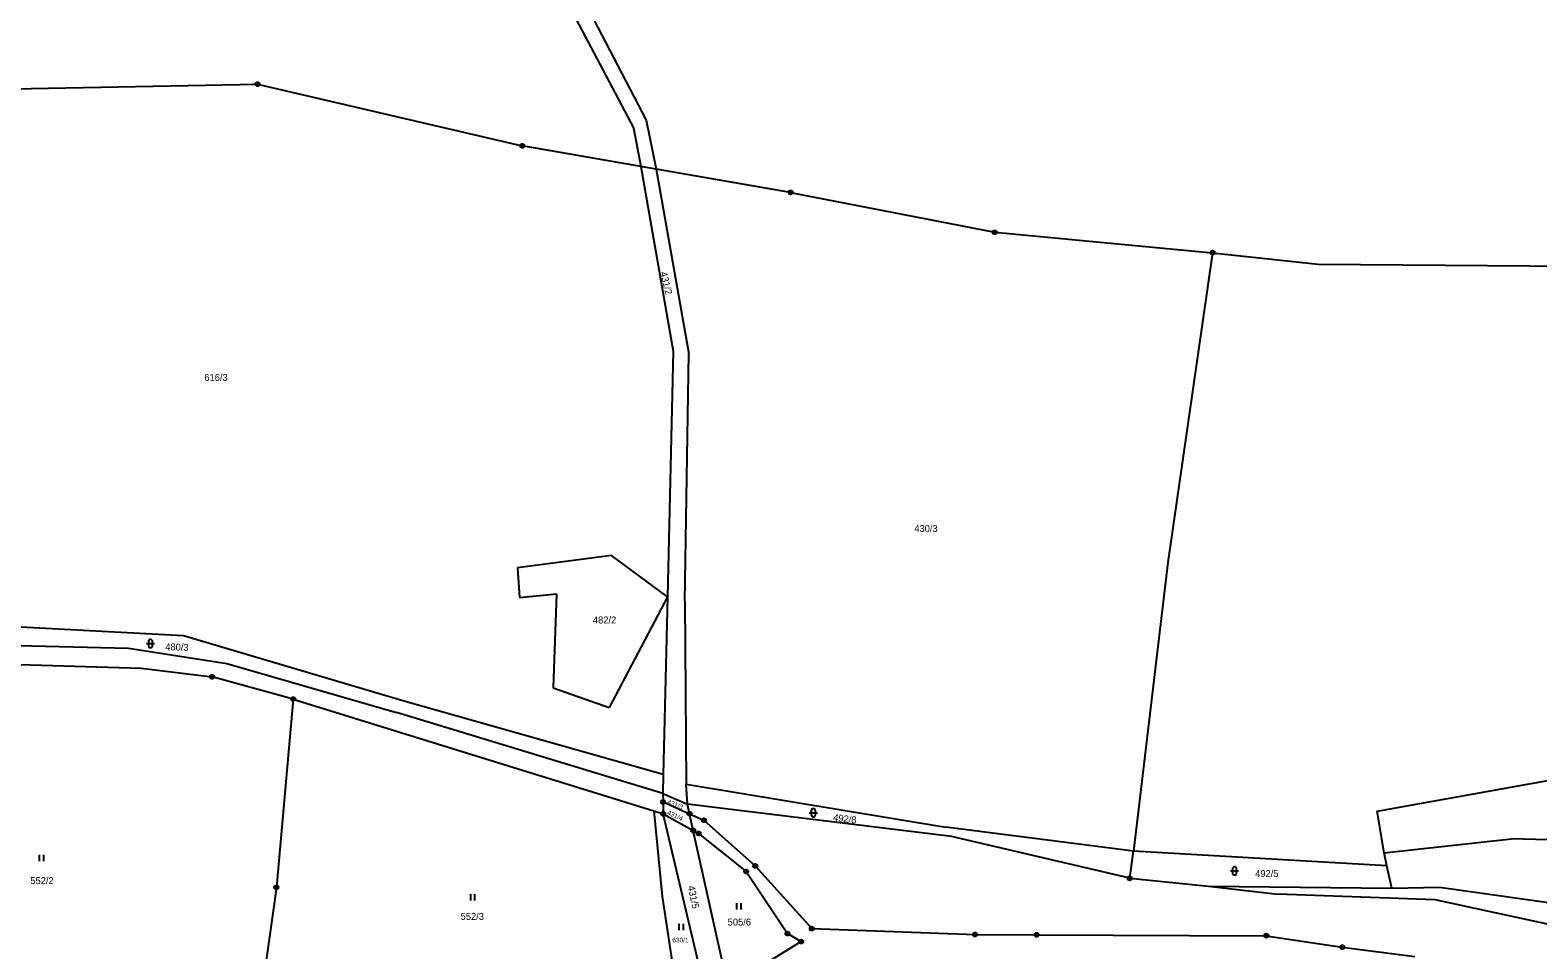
# Model space of a CAD drawing. Extents: x -754970 to -752637, y -970569 to -968179.
# Drawn here: x -754000.8 to -753633.5, y -969199.9 to -968975.7 of the extents above; entities that cross this region are included whole.
import ezdxf
from ezdxf.enums import TextEntityAlignment as Align

# ---------------------------------------------------------------- set-up
doc = ezdxf.new("R2010")
doc.units = 0
doc.header["$LTSCALE"] = 0.68
for name, color, linetype, lineweight in [('1', 7, 'Continuous', 25), ('3', 7, 'Continuous', 25), ('8', 7, 'Continuous', 25)]:
    doc.layers.add(name, color=color, linetype=linetype, lineweight=lineweight)
doc.layers.add('2', color=7, linetype='Continuous')

msp = doc.modelspace()

# ---------------------------------------------------------------- linework, layer by layer
at = {"layer": '1'}
for p, q in [((-753885.65, -968938.96), (-753853.84, -968999.51)), ((-753881.48, -968938.66), (-753850.68, -968997.64)), ((-754015.45, -968990.13), (-753945.4, -968988.82)), ((-753945.4, -968988.82), (-753880.91, -969003.87)), ((-753850.68, -968997.64), (-753848.28, -969009.53)), ((-753853.84, -968999.51), (-753851.99, -969008.89)), ((-753851.99, -969008.89), (-753880.91, -969003.87)), ((-753848.28, -969009.53), (-753851.99, -969008.89)), ((-753851.99, -969008.89), (-753844.1, -969053.94)), ((-753815.54, -969015.22), (-753848.28, -969009.53)), ((-753848.28, -969009.53), (-753840.29, -969054.54)), ((-753815.54, -969015.22), (-753765.79, -969024.92)), ((-753765.79, -969024.92), (-753712.72, -969029.91)), ((-753712.72, -969029.91), (-753723.59, -969105.43)), ((-753712.72, -969029.91), (-753686.97, -969032.69)), ((-753686.97, -969032.69), (-753606.2, -969033.38)), ((-753844.1, -969053.94), (-753845.54, -969113.83)), ((-753841.3, -969114.89), (-753840.29, -969054.54)), ((-753859.15, -969103.73), (-753882.07, -969106.77)), ((-753845.54, -969113.83), (-753859.15, -969103.73)), ((-753723.59, -969105.43), (-753732.02, -969175.76)), ((-753882.07, -969106.77), (-753881.57, -969113.97)), ((-753881.57, -969113.97), (-753872.54, -969113.06)), ((-753872.54, -969113.06), (-753873.35, -969135.99)), ((-753845.54, -969113.83), (-753859.76, -969140.76)), ((-753845.54, -969113.83), (-753846.58, -969157.07)), ((-753841.3, -969114.89), (-753841, -969159.46)), ((-753963.44, -969123.34), (-754006.18, -969121.04)), ((-753909.46, -969139.34), (-753963.44, -969123.34)), ((-754007.16, -969125.58), (-753976.83, -969126.3)), ((-753976.83, -969126.3), (-753952.92, -969130.04)), ((-754008.82, -969130.14), (-753973.75, -969131.19)), ((-753973.75, -969131.19), (-753956.49, -969133.31)), ((-753952.92, -969130.04), (-753911.53, -969141.99)), ((-753936.72, -969138.72), (-753956.49, -969133.31)), ((-753873.35, -969135.99), (-753859.76, -969140.76)), ((-753936.72, -969138.72), (-753940.81, -969184.6)), ((-753936.72, -969138.72), (-753848.84, -969165.98)), ((-753846.64, -969161.75), (-753911.53, -969141.99)), ((-753846.58, -969157.07), (-753909.46, -969139.34)), ((-753846.58, -969157.07), (-753846.64, -969161.75)), ((-753840.67, -969164.36), (-753841, -969159.46)), ((-753841, -969159.46), (-753777.74, -969169.95)), ((-753846.64, -969161.75), (-753840.67, -969164.36)), ((-753846.64, -969161.75), (-753846.6, -969163.79)), ((-753846.6, -969163.79), (-753840.16, -969166.68)), ((-753846.6, -969163.79), (-753846.55, -969166.69)), ((-753848.84, -969165.98), (-753846.8, -969186.86)), ((-753848.84, -969165.98), (-753846.55, -969166.69)), ((-753836.16, -969210.54), (-753846.55, -969166.69)), ((-753846.55, -969166.69), (-753839.25, -969170.77)), ((-753776.35, -969172.22), (-753840.67, -969164.36)), ((-753840.16, -969166.68), (-753840.67, -969164.36)), ((-753840.16, -969166.68), (-753836.63, -969168.26)), ((-753839.25, -969170.77), (-753840.16, -969166.68)), ((-753839.25, -969170.77), (-753837.95, -969171.49)), ((-753830.99, -969207.99), (-753839.25, -969170.77)), ((-753837.95, -969171.49), (-753826.36, -969180.76)), ((-753836.63, -969168.26), (-753824.13, -969179.39)), ((-753732.02, -969175.76), (-753777.74, -969169.95)), ((-753732.9, -969182.41), (-753776.35, -969172.22)), ((-753670.95, -969176.18), (-753639.89, -969172.78)), ((-753625.01, -969173.18), (-753639.89, -969172.78)), ((-753732.9, -969182.41), (-753732.02, -969175.76)), ((-753670.28, -969179.39), (-753732.02, -969175.76)), ((-753670.28, -969179.39), (-753670.95, -969176.18)), ((-753826.36, -969180.76), (-753816.28, -969195.89)), ((-753824.13, -969179.39), (-753810.37, -969194.67)), ((-753732.9, -969182.41), (-753713.68, -969184.29)), ((-753669.06, -969184.83), (-753670.28, -969179.39)), ((-753940.81, -969184.6), (-753947.3, -969231.15)), ((-753713.68, -969184.29), (-753669.06, -969184.83)), ((-753713.68, -969184.29), (-753696.81, -969186.29)), ((-753658.53, -969187.62), (-753696.81, -969186.29)), ((-753669.06, -969184.83), (-753657.41, -969184.61)), ((-753657.41, -969184.61), (-753569.09, -969196.93)), ((-753846.8, -969186.86), (-753842.52, -969215.46)), ((-753602.27, -969199.82), (-753658.53, -969187.62)), ((-753816.28, -969195.89), (-753812.96, -969197.84)), ((-753810.37, -969194.67), (-753770.6, -969196.11)), ((-753770.6, -969196.11), (-753755.61, -969196.18)), ((-753755.61, -969196.18), (-753699.64, -969196.4)), ((-753699.64, -969196.4), (-753681.12, -969199.2)), ((-753812.96, -969197.84), (-753827.73, -969206.99)), ((-753681.12, -969199.2), (-753663.47, -969201.44))]:
    msp.add_line(p, q, dxfattribs=at)
msp.add_lwpolyline([(-753670.95, -969176.18), (-753672.61, -969166.08), (-753588.07, -969150.87)], dxfattribs=at)
at = {"layer": '3'}
for p, q in [((-753972.491, -969125.181), (-753970.489, -969125.181)), ((-753971.991, -969124.681), (-753971.991, -969125.682)), ((-753970.989, -969125.682), (-753970.989, -969124.681)), ((-753810.981, -969166.441), (-753808.979, -969166.441)), ((-753810.481, -969165.941), (-753810.481, -969166.942)), ((-753809.479, -969166.942), (-753809.479, -969165.941)), ((-753998.501, -969178.2), (-753998.501, -969176.7)), ((-753997.5, -969178.2), (-753997.5, -969176.7)), ((-753708.371, -969180.601), (-753706.369, -969180.601)), ((-753707.871, -969180.101), (-753707.871, -969181.102)), ((-753706.869, -969181.102), (-753706.869, -969180.101)), ((-753893.451, -969187.79), (-753893.451, -969186.29)), ((-753892.45, -969187.79), (-753892.45, -969186.29)), ((-753828.601, -969189.98), (-753828.601, -969188.48)), ((-753827.6, -969189.98), (-753827.6, -969188.48)), ((-753842.651, -969195.03), (-753842.651, -969193.53)), ((-753841.65, -969195.03), (-753841.65, -969193.53))]:
    msp.add_line(p, q, dxfattribs=at)
for centre, start, end in [((-753971.49, -969124.6809), 0, 180), ((-753971.49, -969125.6809), 180, 359.98789), ((-753809.98, -969165.9409), 0, 180), ((-753809.98, -969166.9409), 180, 359.98789), ((-753707.37, -969180.1009), 0, 180), ((-753707.37, -969181.1009), 180, 359.98789)]:
    msp.add_arc(centre, 0.5, start, end, dxfattribs=at)
at = {"layer": '8'}
for centre, radius in [((-753945.4, -968988.8199), 0.5), ((-753945.4, -968988.8199), 0.0303), ((-753880.91, -969003.8699), 0.5), ((-753880.91, -969003.8699), 0.0303), ((-753815.54, -969015.2199), 0.5), ((-753815.54, -969015.2199), 0.0303), ((-753765.79, -969024.9199), 0.5), ((-753765.79, -969024.9199), 0.0303), ((-753712.72, -969029.9099), 0.5), ((-753712.72, -969029.9099), 0.0303), ((-753956.49, -969133.3099), 0.5), ((-753956.49, -969133.3099), 0.0303), ((-753936.72, -969138.7199), 0.5), ((-753936.72, -969138.7199), 0.0303), ((-753846.6, -969163.7899), 0.5), ((-753846.6, -969163.7899), 0.0303), ((-753846.55, -969166.6899), 0.5), ((-753846.55, -969166.6899), 0.0303), ((-753840.16, -969166.6799), 0.5), ((-753840.16, -969166.6799), 0.0303), ((-753836.63, -969168.2599), 0.5), ((-753839.25, -969170.7699), 0.5), ((-753839.25, -969170.7699), 0.0303), ((-753837.95, -969171.4899), 0.5), ((-753837.95, -969171.4899), 0.0303), ((-753836.63, -969168.2599), 0.0303), ((-753824.13, -969179.3899), 0.5), ((-753826.36, -969180.7599), 0.5), ((-753826.36, -969180.7599), 0.0303), ((-753824.13, -969179.3899), 0.0303), ((-753732.9, -969182.4099), 0.5), ((-753732.9, -969182.4099), 0.0303), ((-753940.81, -969184.5999), 0.5), ((-753940.81, -969184.5999), 0.0303), ((-753816.28, -969195.8899), 0.5), ((-753816.28, -969195.8899), 0.0303), ((-753810.37, -969194.6699), 0.5), ((-753810.37, -969194.6699), 0.0303), ((-753770.6, -969196.1099), 0.5), ((-753770.6, -969196.1099), 0.0303), ((-753755.61, -969196.1799), 0.5), ((-753755.61, -969196.1799), 0.0303), ((-753699.64, -969196.3999), 0.5), ((-753699.64, -969196.3999), 0.0303), ((-753812.96, -969197.8399), 0.5), ((-753812.96, -969197.8399), 0.0303), ((-753681.12, -969199.1999), 0.5), ((-753681.12, -969199.1999), 0.0303)]:
    msp.add_circle(centre, radius, dxfattribs=at)

# ---------------------------------------------------------------- texts
at = {"layer": '2'}
for s, height, rotation, p in [('431/2', 1.7, 284, (-753846.6457, -969037.5269)), ('480/3', 1.7, 358, (-753965.0597, -969126.8945)), ('431/3', 1.14, 338, (-753843.848, -969164.9473)), ('492/8', 1.7, 353, (-753802.4081, -969168.7381)), ('431/5', 1.7, 282, (-753840.0163, -969187.1678))]:
    msp.add_text(s, height=height, rotation=rotation, dxfattribs=at).set_placement(p, align=Align.CENTER)
for s, height, p in [('616/3', 1.7, (-753955.52, -969061.175)), ('430/3', 1.7, (-753782.55, -969097.995)), ('482/2', 1.7, (-753860.86, -969120.295)), ('552/2', 1.7, (-753997.91, -969183.825)), ('492/5', 1.7, (-753699.51, -969182.095)), ('552/3', 1.7, (-753893.08, -969192.545)), ('505/6', 1.7, (-753828.02, -969193.925)), ('630/1', 1.14, (-753842.359, -969198.045))]:
    msp.add_text(s, height=height, dxfattribs=at).set_placement(p, align=Align.CENTER)
at = {"layer": '2', "width": 1.05}
msp.add_text('431/4', height=1.14, rotation=335, dxfattribs=at).set_placement((-753843.9079, -969167.6249), align=Align.CENTER)

doc.saveas('drawing.dxf')
